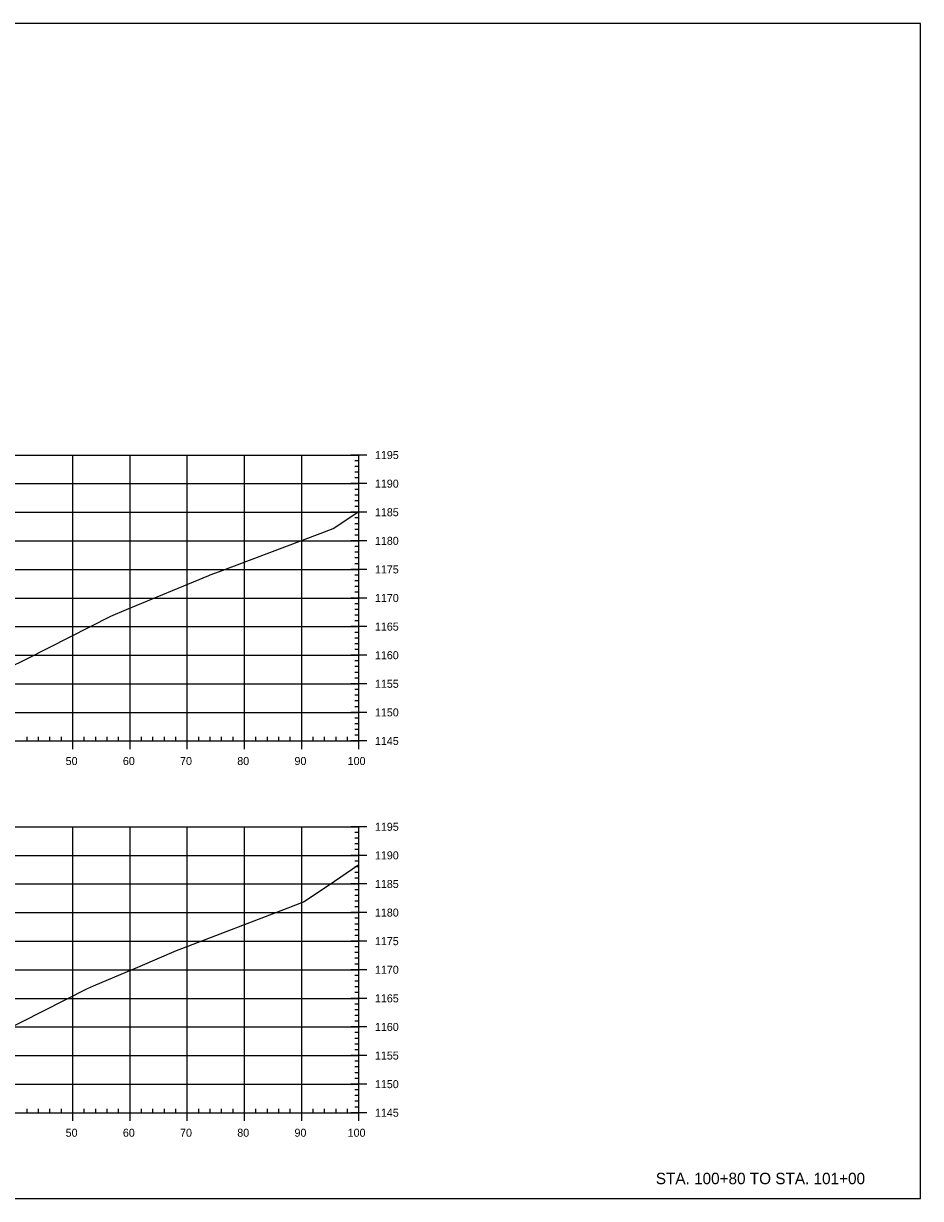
# Model space of a CAD drawing. Extents: x 688474 to 694748, y 765018 to 767373.
# Drawn here: x 689779.2 to 689936, y 765584.1 to 765789.5 of the extents above; entities that cross this region are included whole.
import ezdxf

# ---------------------------------------------------------------- set-up
doc = ezdxf.new("R2010")
doc.units = 0
for name, color, linetype in [('60', 7, 'Continuous'), ('R_Exist Surface', 7, 'Continuous'), ('R_Grid', 7, 'Continuous'), ('R_No Plot', 7, 'Continuous')]:
    doc.layers.add(name, color=color, linetype=linetype)

msp = doc.modelspace()

# ---------------------------------------------------------------- linework, layer by layer
at = {"layer": '60'}
for p, q in [((689839.22, 765714.06), (689836.42, 765714.06)), ((689837.82, 765713.06), (689837.12, 765713.06)), ((689837.82, 765664.06), (689837.82, 765714.06)), ((689837.82, 765712.06), (689837.12, 765712.06)), ((689837.82, 765711.06), (689837.12, 765711.06)), ((689839.22, 765709.06), (689836.42, 765709.06)), ((689837.82, 765710.06), (689837.12, 765710.06)), ((689837.82, 765708.06), (689837.12, 765708.06)), ((689837.82, 765707.06), (689837.12, 765707.06)), ((689837.82, 765706.06), (689837.12, 765706.06)), ((689837.82, 765705.06), (689837.12, 765705.06)), ((689839.22, 765704.06), (689836.42, 765704.06)), ((689837.82, 765703.06), (689837.12, 765703.06)), ((689837.82, 765702.06), (689837.12, 765702.06)), ((689837.82, 765701.06), (689837.12, 765701.06)), ((689839.22, 765699.06), (689836.42, 765699.06)), ((689837.82, 765700.06), (689837.12, 765700.06)), ((689837.82, 765698.06), (689837.12, 765698.06)), ((689837.82, 765697.06), (689837.12, 765697.06)), ((689837.82, 765696.06), (689837.12, 765696.06)), ((689839.22, 765694.06), (689836.42, 765694.06)), ((689837.82, 765695.06), (689837.12, 765695.06)), ((689837.82, 765693.06), (689837.12, 765693.06)), ((689837.82, 765692.06), (689837.12, 765692.06)), ((689837.82, 765691.06), (689837.12, 765691.06)), ((689837.82, 765690.06), (689837.12, 765690.06)), ((689839.22, 765689.06), (689836.42, 765689.06)), ((689837.82, 765688.06), (689837.12, 765688.06)), ((689837.82, 765687.06), (689837.12, 765687.06)), ((689837.82, 765686.06), (689837.12, 765686.06)), ((689839.22, 765684.06), (689836.42, 765684.06)), ((689837.82, 765685.06), (689837.12, 765685.06)), ((689837.82, 765683.06), (689837.12, 765683.06)), ((689837.82, 765682.06), (689837.12, 765682.06)), ((689837.82, 765681.06), (689837.12, 765681.06)), ((689837.82, 765680.06), (689837.12, 765680.06)), ((689839.22, 765679.06), (689836.42, 765679.06)), ((689837.82, 765678.06), (689837.12, 765678.06)), ((689837.82, 765677.06), (689837.12, 765677.06)), ((689837.82, 765676.06), (689837.12, 765676.06)), ((689839.22, 765674.06), (689836.42, 765674.06)), ((689837.82, 765675.06), (689837.12, 765675.06)), ((689837.82, 765673.06), (689837.12, 765673.06)), ((689837.82, 765672.06), (689837.12, 765672.06)), ((689837.82, 765671.06), (689837.12, 765671.06)), ((689837.82, 765670.06), (689837.12, 765670.06)), ((689839.22, 765669.06), (689836.42, 765669.06)), ((689837.82, 765668.06), (689837.12, 765668.06)), ((689787.82, 765662.66), (689787.82, 765665.46)), ((689797.82, 765662.66), (689797.82, 765665.46)), ((689807.82, 765662.66), (689807.82, 765665.46)), ((689817.82, 765662.66), (689817.82, 765665.46)), ((689827.82, 765662.66), (689827.82, 765665.46)), ((689837.82, 765667.06), (689837.12, 765667.06)), ((689837.82, 765666.06), (689837.12, 765666.06)), ((689837.82, 765662.66), (689837.82, 765665.46)), ((689637.82, 765664.06), (689837.82, 765664.06)), ((689779.82, 765664.06), (689779.82, 765664.76)), ((689781.82, 765664.06), (689781.82, 765664.76)), ((689783.82, 765664.06), (689783.82, 765664.76)), ((689785.82, 765664.06), (689785.82, 765664.76)), ((689789.82, 765664.06), (689789.82, 765664.76)), ((689791.82, 765664.06), (689791.82, 765664.76)), ((689793.82, 765664.06), (689793.82, 765664.76)), ((689795.82, 765664.06), (689795.82, 765664.76)), ((689799.82, 765664.06), (689799.82, 765664.76)), ((689801.82, 765664.06), (689801.82, 765664.76)), ((689803.82, 765664.06), (689803.82, 765664.76)), ((689805.82, 765664.06), (689805.82, 765664.76)), ((689809.82, 765664.06), (689809.82, 765664.76)), ((689811.82, 765664.06), (689811.82, 765664.76)), ((689813.82, 765664.06), (689813.82, 765664.76)), ((689815.82, 765664.06), (689815.82, 765664.76)), ((689819.82, 765664.06), (689819.82, 765664.76)), ((689821.82, 765664.06), (689821.82, 765664.76)), ((689823.82, 765664.06), (689823.82, 765664.76)), ((689825.82, 765664.06), (689825.82, 765664.76)), ((689829.82, 765664.06), (689829.82, 765664.76)), ((689831.82, 765664.06), (689831.82, 765664.76)), ((689833.82, 765664.06), (689833.82, 765664.76)), ((689835.82, 765664.06), (689835.82, 765664.76)), ((689839.22, 765664.06), (689836.42, 765664.06)), ((689837.82, 765665.06), (689837.12, 765665.06)), ((689839.22, 765649.06), (689836.42, 765649.06)), ((689837.82, 765599.06), (689837.82, 765649.06)), ((689837.82, 765648.06), (689837.12, 765648.06)), ((689837.82, 765647.06), (689837.12, 765647.06)), ((689837.82, 765646.06), (689837.12, 765646.06)), ((689837.82, 765645.06), (689837.12, 765645.06)), ((689839.22, 765644.06), (689836.42, 765644.06)), ((689837.82, 765643.06), (689837.12, 765643.06)), ((689837.82, 765642.06), (689837.12, 765642.06)), ((689837.82, 765641.06), (689837.12, 765641.06)), ((689839.22, 765639.06), (689836.42, 765639.06)), ((689837.82, 765640.06), (689837.12, 765640.06)), ((689837.82, 765638.06), (689837.12, 765638.06)), ((689837.82, 765637.06), (689837.12, 765637.06)), ((689837.82, 765636.06), (689837.12, 765636.06)), ((689837.82, 765635.06), (689837.12, 765635.06)), ((689839.22, 765634.06), (689836.42, 765634.06)), ((689837.82, 765633.06), (689837.12, 765633.06)), ((689837.82, 765632.06), (689837.12, 765632.06)), ((689837.82, 765631.06), (689837.12, 765631.06)), ((689839.22, 765629.06), (689836.42, 765629.06)), ((689837.82, 765630.06), (689837.12, 765630.06)), ((689837.82, 765628.06), (689837.12, 765628.06)), ((689837.82, 765627.06), (689837.12, 765627.06)), ((689837.82, 765626.06), (689837.12, 765626.06)), ((689837.82, 765625.06), (689837.12, 765625.06)), ((689839.22, 765624.06), (689836.42, 765624.06)), ((689837.82, 765623.06), (689837.12, 765623.06)), ((689837.82, 765622.06), (689837.12, 765622.06)), ((689837.82, 765621.06), (689837.12, 765621.06)), ((689837.82, 765620.06), (689837.12, 765620.06)), ((689839.22, 765619.06), (689836.42, 765619.06)), ((689837.82, 765618.06), (689837.12, 765618.06)), ((689837.82, 765617.06), (689837.12, 765617.06)), ((689837.82, 765616.06), (689837.12, 765616.06)), ((689839.22, 765614.06), (689836.42, 765614.06)), ((689837.82, 765615.06), (689837.12, 765615.06)), ((689837.82, 765613.06), (689837.12, 765613.06)), ((689837.82, 765612.06), (689837.12, 765612.06)), ((689837.82, 765611.06), (689837.12, 765611.06)), ((689837.82, 765610.06), (689837.12, 765610.06)), ((689839.22, 765609.06), (689836.42, 765609.06)), ((689837.82, 765608.06), (689837.12, 765608.06)), ((689837.82, 765607.06), (689837.12, 765607.06)), ((689837.82, 765606.06), (689837.12, 765606.06)), ((689839.22, 765604.06), (689836.42, 765604.06)), ((689837.82, 765605.06), (689837.12, 765605.06)), ((689837.82, 765603.06), (689837.12, 765603.06)), ((689837.82, 765602.06), (689837.12, 765602.06)), ((689779.82, 765599.06), (689779.82, 765599.76)), ((689781.82, 765599.06), (689781.82, 765599.76)), ((689783.82, 765599.06), (689783.82, 765599.76)), ((689785.82, 765599.06), (689785.82, 765599.76)), ((689787.82, 765597.66), (689787.82, 765600.46)), ((689789.82, 765599.06), (689789.82, 765599.76)), ((689791.82, 765599.06), (689791.82, 765599.76)), ((689793.82, 765599.06), (689793.82, 765599.76)), ((689795.82, 765599.06), (689795.82, 765599.76)), ((689797.82, 765597.66), (689797.82, 765600.46)), ((689799.82, 765599.06), (689799.82, 765599.76)), ((689801.82, 765599.06), (689801.82, 765599.76)), ((689803.82, 765599.06), (689803.82, 765599.76)), ((689805.82, 765599.06), (689805.82, 765599.76)), ((689807.82, 765597.66), (689807.82, 765600.46)), ((689809.82, 765599.06), (689809.82, 765599.76)), ((689811.82, 765599.06), (689811.82, 765599.76)), ((689813.82, 765599.06), (689813.82, 765599.76)), ((689815.82, 765599.06), (689815.82, 765599.76)), ((689817.82, 765597.66), (689817.82, 765600.46)), ((689819.82, 765599.06), (689819.82, 765599.76)), ((689821.82, 765599.06), (689821.82, 765599.76)), ((689823.82, 765599.06), (689823.82, 765599.76)), ((689825.82, 765599.06), (689825.82, 765599.76)), ((689827.82, 765597.66), (689827.82, 765600.46)), ((689829.82, 765599.06), (689829.82, 765599.76)), ((689831.82, 765599.06), (689831.82, 765599.76)), ((689833.82, 765599.06), (689833.82, 765599.76)), ((689835.82, 765599.06), (689835.82, 765599.76)), ((689837.82, 765601.06), (689837.12, 765601.06)), ((689837.82, 765600.06), (689837.12, 765600.06)), ((689837.82, 765597.66), (689837.82, 765600.46)), ((689637.82, 765599.06), (689837.82, 765599.06)), ((689839.22, 765599.06), (689836.42, 765599.06))]:
    msp.add_line(p, q, dxfattribs=at)
at = {"layer": 'R_Exist Surface'}
for points in [[(689776.24, 765676.65), (689780, 765678.55), (689794.45, 765685.88), (689797.18, 765687.05), (689811.61, 765693.02), (689811.82, 765693.1), (689813.44, 765693.71), (689831.03, 765700.37), (689833.3, 765701.21), (689837.82, 765704.21)], [(689774.93, 765612.96), (689790.39, 765620.76), (689791.45, 765621.24), (689799.56, 765624.69), (689805.96, 765627.43), (689806.86, 765627.8), (689825.44, 765634.9), (689828.13, 765635.92), (689832.44, 765638.81), (689837.82, 765642.46)]]:
    msp.add_lwpolyline(points, dxfattribs=at)
at = {"layer": 'R_Grid'}
for p, q in [((689637.82, 765714.06), (689837.82, 765714.06)), ((689787.82, 765664.06), (689787.82, 765714.06)), ((689797.82, 765664.06), (689797.82, 765714.06)), ((689807.82, 765664.06), (689807.82, 765714.06)), ((689817.82, 765664.06), (689817.82, 765714.06)), ((689827.82, 765664.06), (689827.82, 765714.06)), ((689837.82, 765664.06), (689837.82, 765714.06)), ((689637.82, 765709.06), (689837.82, 765709.06)), ((689637.82, 765704.06), (689837.82, 765704.06)), ((689637.82, 765699.06), (689837.82, 765699.06)), ((689637.82, 765694.06), (689837.82, 765694.06)), ((689637.82, 765689.06), (689837.82, 765689.06)), ((689637.82, 765684.06), (689837.82, 765684.06)), ((689637.82, 765679.06), (689837.82, 765679.06)), ((689637.82, 765674.06), (689837.82, 765674.06)), ((689637.82, 765669.06), (689837.82, 765669.06)), ((689637.82, 765664.06), (689837.82, 765664.06)), ((689637.82, 765649.06), (689837.82, 765649.06)), ((689787.82, 765599.06), (689787.82, 765649.06)), ((689797.82, 765599.06), (689797.82, 765649.06)), ((689807.82, 765599.06), (689807.82, 765649.06)), ((689817.82, 765599.06), (689817.82, 765649.06)), ((689827.82, 765599.06), (689827.82, 765649.06)), ((689837.82, 765599.06), (689837.82, 765649.06)), ((689637.82, 765644.06), (689837.82, 765644.06)), ((689637.82, 765639.06), (689837.82, 765639.06)), ((689637.82, 765634.06), (689837.82, 765634.06)), ((689637.82, 765629.06), (689837.82, 765629.06)), ((689637.82, 765624.06), (689837.82, 765624.06)), ((689637.82, 765619.06), (689837.82, 765619.06)), ((689637.82, 765614.06), (689837.82, 765614.06)), ((689637.82, 765609.06), (689837.82, 765609.06)), ((689637.82, 765604.06), (689837.82, 765604.06)), ((689637.82, 765599.06), (689837.82, 765599.06))]:
    msp.add_line(p, q, dxfattribs=at)
at = {"layer": 'R_No Plot'}
msp.add_lwpolyline([(689619.82, 765584.06), (689936, 765584.06), (689936, 765789.52), (689619.82, 765789.52)], close=True, dxfattribs=at)

# ---------------------------------------------------------------- texts
at = {"layer": '60'}
for s, height, p in [('1195', 1.4, (689840.62, 765713.36)), ('1190', 1.4, (689840.62, 765708.36)), ('1185', 1.4, (689840.62, 765703.36)), ('1180', 1.4, (689840.62, 765698.36)), ('1175', 1.4, (689840.62, 765693.36)), ('1170', 1.4, (689840.62, 765688.36)), ('1165', 1.4, (689840.62, 765683.36)), ('1160', 1.4, (689840.62, 765678.36)), ('1155', 1.4, (689840.62, 765673.36)), ('1150', 1.4, (689840.62, 765668.36)), ('1145', 1.4, (689840.62, 765663.36)), ('50', 1.4, (689786.56, 765659.86)), ('60', 1.4, (689796.56, 765659.86)), ('70', 1.4, (689806.56, 765659.86)), ('80', 1.4, (689816.56, 765659.86)), ('90', 1.4, (689826.56, 765659.86)), ('100', 1.4, (689835.86, 765659.86)), ('1195', 1.4, (689840.62, 765648.36)), ('1190', 1.4, (689840.62, 765643.36)), ('1185', 1.4, (689840.62, 765638.36)), ('1180', 1.4, (689840.62, 765633.36)), ('1175', 1.4, (689840.62, 765628.36)), ('1170', 1.4, (689840.62, 765623.36)), ('1165', 1.4, (689840.62, 765618.36)), ('1160', 1.4, (689840.62, 765613.36)), ('1155', 1.4, (689840.62, 765608.36)), ('1150', 1.4, (689840.62, 765603.36)), ('1145', 1.4, (689840.62, 765598.36)), ('50', 1.4, (689786.56, 765594.86)), ('60', 1.4, (689796.56, 765594.86)), ('70', 1.4, (689806.56, 765594.86)), ('80', 1.4, (689816.56, 765594.86)), ('90', 1.4, (689826.56, 765594.86)), ('100', 1.4, (689835.86, 765594.86)), ('STA. 100+80 TO STA. 101+00', 2, (689889.73, 765586.56))]:
    msp.add_text(s, height=height, dxfattribs=at).set_placement(p)

doc.saveas('drawing.dxf')
